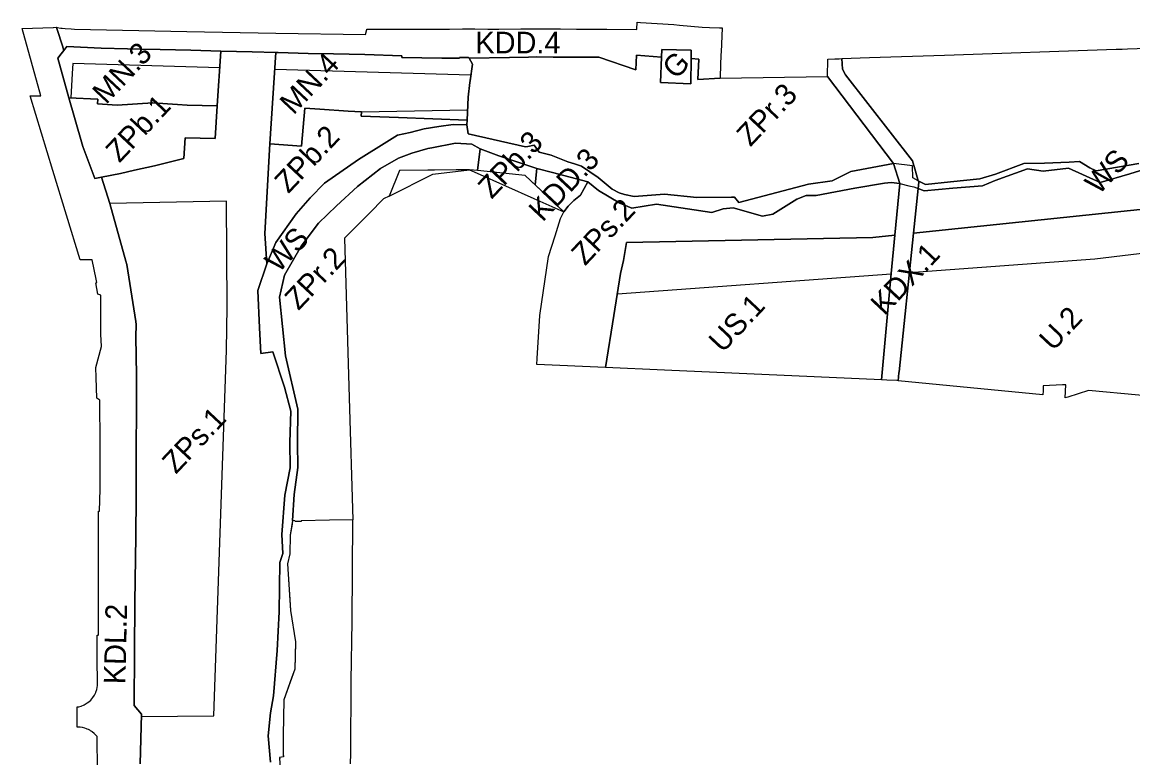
# Model space of a CAD drawing. Extents: x 7425782 to 7428854, y 5550411 to 5553074.
# Drawn here: x 7425924.4 to 7426386.8, y 5550791.4 to 5551098 of the extents above; entities that cross this region are included whole.
import ezdxf

# ---------------------------------------------------------------- set-up
doc = ezdxf.new("R2010")
doc.units = 0
for name, color, linetype in [('LIN_Linie rozgraniczajace WS', 7, 'Continuous'), ('LIN_linie_rozgraniczajace', 7, 'Continuous'), ('LIN_nieprzekraczalna linia zabudowy', 7, 'Continuous'), ('tereny MPZP_PRADNIK_CZERWONY_NACZELNA', 7, 'Continuous'), ('TXT_oznaczenia przeznaczen', 7, 'Continuous')]:
    doc.layers.add(name, color=color, linetype=linetype)

msp = doc.modelspace()

# ---------------------------------------------------------------- linework, layer by layer
at = {"layer": 'LIN_Linie rozgraniczajace WS'}
for points in [[(7426297.5, 5551031.91), (7426295.16, 5551033.1), (7426295.12, 5551038.07), (7426287.1, 5551039.04)], [(7426289.82, 5551030.77), (7426293.58, 5551029.75), (7426295.69, 5551029.3), (7426297.42, 5551028.65)]]:
    msp.add_lwpolyline(points, dxfattribs=at)
at = {"layer": 'LIN_linie_rozgraniczajace'}
for points in [[(7426215.8, 5551095.6), (7426215.39, 5551085.51), (7426215.34, 5551084.42), (7426214.98, 5551075.35), (7426214.95, 5551074.7), (7426214.95, 5551074.69), (7426214.94, 5551074.57), (7426214.94, 5551074.57), (7426205.64, 5551074.12), (7426206.09, 5551082.55), (7426202.86, 5551082.78), (7426202.86, 5551086.29), (7426190.75, 5551086.61), (7426190.63, 5551083.44), (7426180.21, 5551084.26), (7426179.84, 5551078.14), (7426164.44, 5551083.38), (7426145.43, 5551083.43), (7426138.5, 5551083.48), (7426135.17, 5551083.31), (7426127.25, 5551083.21), (7426110.43, 5551082.92), (7426110.23, 5551083.26), (7426106.54, 5551083.3), (7426106.49, 5551082.9), (7426099.18, 5551083.01), (7426082.44, 5551083.24), (7426082.45, 5551083.98), (7426067.06, 5551084.42), (7426053.98, 5551084.79), (7426043.49, 5551084.97), (7426031.04, 5551085.35), (7426030.05, 5551085.39), (7426020.19, 5551085.58), (7426007.07, 5551085.94), (7425994.58, 5551086.3), (7425981.88, 5551086.56), (7425973.98, 5551086.7), (7425968.18, 5551086.79), (7425957.28, 5551087.07), (7425943.02, 5551087.82), (7425941.71, 5551086.16), (7425941.19, 5551088.09), (7425938.94, 5551094.9), (7425938.67, 5551095.85), (7425938.67, 5551095.85), (7425938.69, 5551095.85), (7425938.72, 5551095.84), (7425938.98, 5551095.8), (7425940.5, 5551095.53), (7425940.5, 5551095.53), (7425941.08, 5551095.46), (7425942.36, 5551095.32), (7425944.84, 5551095.14), (7425946.25, 5551095.1), (7425946.25, 5551095.1), (7425992.94, 5551094.01), (7426029.97, 5551093.42), (7426067.31, 5551092.83), (7426067.73, 5551094.38), (7426067.8, 5551094.65), (7426067.84, 5551094.78), (7426067.85, 5551094.81), (7426067.89, 5551094.98), (7426097.22, 5551095.1), (7426098.27, 5551095.1), (7426102.29, 5551095.11), (7426107.73, 5551095.13), (7426109.94, 5551095.14), (7426111.53, 5551095.14), (7426111.54, 5551095.14), (7426111.55, 5551095.14), (7426112.79, 5551095.14), (7426112.85, 5551095.14), (7426118.27, 5551095.11), (7426122.78, 5551095.09), (7426132.03, 5551095.12), (7426148.58, 5551095.17), (7426155.17, 5551095.11), (7426155.17, 5551095.11), (7426160.39, 5551095.07), (7426167.87, 5551095.01), (7426180.28, 5551094.91), (7426180.28, 5551094.91), (7426180.29, 5551094.99), (7426180.29, 5551095), (7426180.29, 5551095.01), (7426180.5, 5551097.95), (7426181.8, 5551097.87), (7426195.75, 5551097), (7426198.06, 5551096.78), (7426207.49, 5551095.89), (7426207.53, 5551095.88), (7426210.49, 5551095.78), (7426214.7, 5551095.64)], [(7426007.07, 5551085.94), (7426005.64, 5551063.03), (7425993.14, 5551063.4), (7425989.01, 5551063.61), (7425978.85, 5551064.28), (7425963.96, 5551063.32), (7425955.74, 5551063.87), (7425955.87, 5551065.84), (7425943.81, 5551066.48), (7425939.19, 5551082.96), (7425940.63, 5551084.79), (7425941.71, 5551086.16), (7425943.02, 5551087.82), (7425957.28, 5551087.07), (7425968.18, 5551086.79), (7425973.98, 5551086.7), (7425981.88, 5551086.56), (7425994.58, 5551086.3)], [(7426110.43, 5551082.92), (7426111.9, 5551080.41), (7426110.91, 5551073.53), (7426110.81, 5551072.81), (7426110.08, 5551066.7), (7426109.62, 5551057.17), (7426081.04, 5551058.3), (7426065.52, 5551058.75), (7426065.63, 5551060.55), (7426060.18, 5551060.89), (7426048.37, 5551061.72), (7426042.01, 5551062.19), (7426040.71, 5551046.28), (7426027.51, 5551047.29), (7426030.05, 5551085.39), (7426031.04, 5551085.35), (7426043.49, 5551084.97), (7426053.98, 5551084.79), (7426067.06, 5551084.42), (7426082.45, 5551083.98), (7426082.44, 5551083.24), (7426099.18, 5551083.01), (7426106.49, 5551082.9), (7426106.54, 5551083.3), (7426110.23, 5551083.26)], [(7426190.63, 5551083.44), (7426190.15, 5551072.79), (7426202.79, 5551072.25), (7426202.86, 5551082.78), (7426206.09, 5551082.55), (7426205.64, 5551074.12), (7426214.94, 5551074.57), (7426214.94, 5551074.57), (7426259.75, 5551075.32), (7426287.1, 5551039.04), (7426269.36, 5551035.67), (7426261.64, 5551031.9), (7426251.76, 5551030.52), (7426222.72, 5551022.82), (7426220.95, 5551025.02), (7426219.72, 5551025.01), (7426205.23, 5551024.86), (7426191.78, 5551026.27), (7426179.13, 5551025.37), (7426175.11, 5551026.19), (7426172.96, 5551026.84), (7426170.03, 5551028.39), (7426164.25, 5551033.26), (7426157.29, 5551038.02), (7426154.32, 5551038.89), (7426151.51, 5551039.82), (7426148.75, 5551040.91), (7426144.59, 5551042.59), (7426139.7, 5551043.77), (7426137.53, 5551046.7), (7426134.97, 5551046.1), (7426133.89, 5551046.07), (7426110.03, 5551051.47), (7426109.52, 5551055.15), (7426109.62, 5551057.17), (7426110.08, 5551066.7), (7426110.81, 5551072.81), (7426110.91, 5551073.53), (7426111.9, 5551080.41), (7426110.43, 5551082.92), (7426127.25, 5551083.21), (7426135.17, 5551083.31), (7426138.5, 5551083.48), (7426145.43, 5551083.43), (7426164.44, 5551083.38), (7426179.84, 5551078.14), (7426180.21, 5551084.26)], [(7426202.86, 5551082.78), (7426202.79, 5551072.25), (7426190.15, 5551072.79), (7426190.63, 5551083.44), (7426190.75, 5551086.61), (7426202.86, 5551086.29)], [(7426289.39, 5550951.87), (7426289.12, 5550948.57), (7426288.53, 5550948.63), (7426284.35, 5550948.81), (7426282.17, 5550948.91), (7426286.21, 5550993.18), (7426287.75, 5551009.24), (7426289.82, 5551030.77), (7426287.1, 5551039.04), (7426259.75, 5551075.32), (7426259.85, 5551082.6), (7426262.77, 5551082.69), (7426264.5, 5551082.75), (7426265.69, 5551082.79), (7426265.69, 5551082.79), (7426265.99, 5551078.4), (7426267.13, 5551076), (7426295.12, 5551040.16), (7426296.35, 5551035.89), (7426297.5, 5551031.91), (7426297.69, 5551031.25), (7426297.42, 5551028.65), (7426295.49, 5551010.06), (7426289.51, 5550952.33)], [(7426005.64, 5551063.03), (7426004.79, 5551049.53), (7425992.29, 5551049.82), (7425991.74, 5551041.19), (7425979.5, 5551038.1), (7425971.23, 5551036.23), (7425965.37, 5551034.91), (7425957.43, 5551033.37), (7425954.62, 5551032.82), (7425949.65, 5551046.1), (7425946.12, 5551058.23), (7425943.81, 5551066.48), (7425955.87, 5551065.84), (7425955.74, 5551063.87), (7425963.96, 5551063.32), (7425978.85, 5551064.28), (7425989.01, 5551063.61), (7425993.14, 5551063.4)], [(7426109.62, 5551057.17), (7426109.52, 5551055.15), (7426103.78, 5551055.26), (7426097.83, 5551054.54), (7426091.71, 5551053.53), (7426086, 5551052.04), (7426080.63, 5551050.93), (7426076.28, 5551048.15), (7426064.43, 5551040.8), (7426050.28, 5551030.82), (7426044.36, 5551024.77), (7426038.41, 5551018.08), (7426030.06, 5551006.1), (7426026.26, 5550997.32), (7426025.43, 5551009.92), (7426027.51, 5551047.29), (7426040.71, 5551046.28), (7426042.01, 5551062.19), (7426048.37, 5551061.72), (7426060.18, 5551060.89), (7426065.63, 5551060.55), (7426065.52, 5551058.75), (7426081.04, 5551058.3)], [(7426115.04, 5551045.2), (7426114.02, 5551036.11), (7426110.63, 5551036.45), (7426105.05, 5551036.41), (7426081.5, 5551036.22), (7426077.23, 5551025.48), (7426074.88, 5551024.29), (7426069.02, 5551018.4), (7426058.65, 5551007.98), (7426060.56, 5550941.47), (7426062.03, 5550890.54), (7426052.4, 5550890.39), (7426040.5, 5550890.2), (7426040.52, 5550889.93), (7426038.02, 5550889.95), (7426037.95, 5550890.16), (7426037, 5550890.25), (7426037, 5550890.25), (7426037.7, 5550901.21), (7426039.13, 5550912.4), (7426039, 5550922.67), (7426039.23, 5550936.74), (7426034.08, 5550958.93), (7426031.6, 5550983.36), (7426033.64, 5550992.58), (7426040.62, 5551004.69), (7426047.82, 5551014.27), (7426055.24, 5551021.39), (7426064.05, 5551029.53), (7426073.55, 5551037.01), (7426081.06, 5551041.3), (7426086.68, 5551043.41), (7426093.32, 5551045.35), (7426095.01, 5551045.64), (7426104.86, 5551047.6), (7426111.59, 5551047.15)], [(7426138.67, 5551037.01), (7426137.97, 5551030.23), (7426133.83, 5551034.14), (7426114.02, 5551036.11), (7426115.04, 5551045.2), (7426122.91, 5551042.26)], [(7426159.96, 5551031.38), (7426156.85, 5551025.84), (7426154.07, 5551023.59), (7426151.74, 5551021.3), (7426149.94, 5551018.93), (7426137.97, 5551030.23), (7426138.67, 5551037.01), (7426145.22, 5551035.28)], [(7426173.17, 5551022.6), (7426178.19, 5551020.44), (7426188.54, 5551022.09), (7426211.52, 5551018.65), (7426216.26, 5551020.12), (7426220.36, 5551020.54), (7426232.69, 5551017.15), (7426236.9, 5551017.95), (7426246.88, 5551024.24), (7426250.8, 5551025.73), (7426254.93, 5551025.78), (7426271.11, 5551028.73), (7426283.4, 5551030.81), (7426286.14, 5551031.16), (7426289.82, 5551030.77), (7426287.75, 5551009.24), (7426278.49, 5551008.25), (7426175.98, 5551006.17), (7426174.73, 5550998.7), (7426173.57, 5550993.17), (7426170.73, 5550975.7), (7426167.26, 5550954.09), (7426138.63, 5550955.38), (7426138.79, 5550957.78), (7426139.97, 5550975.69), (7426143.56, 5551000.38), (7426146.26, 5551008.87), (7426148.58, 5551016.14), (7426148.58, 5551016.14), (7426149.94, 5551018.93), (7426151.74, 5551021.3), (7426154.07, 5551023.59), (7426156.85, 5551025.84), (7426159.96, 5551031.38), (7426164.34, 5551027.84)], [(7426425.64, 5550954.9), (7426424, 5550939.27), (7426410.3, 5550940.56), (7426368.28, 5550944.5), (7426359.7, 5550941.77), (7426358.59, 5550941.42), (7426358.97, 5550946.87), (7426357.5, 5550946.8), (7426349.51, 5550946.41), (7426349.44, 5550944.41), (7426349.38, 5550942.63), (7426289.12, 5550948.57), (7426289.39, 5550951.87), (7426289.51, 5550952.33), (7426295.49, 5551010.06), (7426429.66, 5551024.14), (7426426.02, 5550961.54), (7426426.02, 5550961.54), (7426425.81, 5550957.91)], [(7426282.17, 5550948.91), (7426191.82, 5550952.98), (7426167.26, 5550954.09), (7426170.73, 5550975.7), (7426173.57, 5550993.17), (7426174.73, 5550998.7), (7426175.98, 5551006.17), (7426278.49, 5551008.25), (7426287.75, 5551009.24), (7426286.21, 5550993.18)]]:
    msp.add_lwpolyline(points, close=True, dxfattribs=at)
for points in [[(7425955.84, 5550771.93), (7425955.61, 5550800.27), (7425955.07, 5550800.85), (7425954.32, 5550801.6), (7425953.58, 5550802.22), (7425953.43, 5550802.34), (7425953.43, 5550802.34), (7425952.86, 5550802.71), (7425952.55, 5550802.91), (7425952.55, 5550802.91), (7425951.97, 5550803.19), (7425951.52, 5550803.41), (7425951.52, 5550803.41), (7425951.21, 5550803.53), (7425950.52, 5550803.78), (7425949.54, 5550804.02), (7425948.52, 5550804.19), (7425947.31, 5550804.22), (7425947.32, 5550810.46), (7425947.32, 5550811.37), (7425947.32, 5550812.63), (7425947.57, 5550812.66), (7425947.95, 5550812.71), (7425948.97, 5550813.01), (7425950.16, 5550813.52), (7425951.07, 5550814.03), (7425951.28, 5550814.15), (7425951.48, 5550814.3), (7425952.09, 5550814.75), (7425952.98, 5550815.51), (7425953.8, 5550816.52), (7425954.45, 5550817.47), (7425955.01, 5550818.64), (7425955.01, 5550818.64), (7425955.06, 5550818.77), (7425955.5, 5550819.95), (7425955.8, 5550821.51), (7425955.68, 5550833.66), (7425955.59, 5550842.56), (7425956.07, 5550842.6), (7425956.22, 5550842.61), (7425956.22, 5550843.47), (7425956.19, 5550858.72), (7425956.19, 5550875.69), (7425956.19, 5550875.69), (7425956.15, 5550894.19), (7425956.66, 5550894.27), (7425956.91, 5550903.41), (7425956.85, 5550914.45), (7425956.83, 5550917.11), (7425956.83, 5550917.11), (7425956.82, 5550922.12), (7425956.78, 5550940.39), (7425955.52, 5550941.23), (7425955.23, 5550949.91), (7425955.09, 5550954.12), (7425957.42, 5550962.88), (7425957.2, 5550967.97), (7425957.2, 5550967.97), (7425957.16, 5550984.24), (7425955.93, 5550984.67), (7425955.09, 5550989.29), (7425955.24, 5550989.33), (7425955.51, 5550989.42), (7425955.22, 5550990.82), (7425953.57, 5550998.88), (7425949.01, 5550998.91), (7425948.54, 5550998.91), (7425937.17, 5551036.17), (7425927.7, 5551067.22), (7425932.1, 5551067.33), (7425932.1, 5551067.33), (7425924.41, 5551095.28), (7425937.34, 5551095.8), (7425937.43, 5551095.8), (7425938.67, 5551095.85), (7425938.67, 5551095.85), (7425938.94, 5551094.9), (7425941.19, 5551088.09), (7425941.71, 5551086.16), (7425940.63, 5551084.79), (7425939.19, 5551082.96), (7425943.81, 5551066.48), (7425946.12, 5551058.23), (7425949.65, 5551046.1), (7425954.62, 5551032.82), (7425957.43, 5551033.37), (7425960.93, 5551022.38), (7425967.55, 5550998.37), (7425967.91, 5550997.05), (7425971.71, 5550973.18), (7425971.85, 5550971.99), (7425971.77, 5550966.88), (7425972.01, 5550950.87), (7425971.95, 5550946.48), (7425971.98, 5550940.06), (7425971.93, 5550935.95), (7425971.89, 5550920.72), (7425971.8, 5550900), (7425971.7, 5550883.82), (7425971.36, 5550856.12), (7425971.17, 5550835.7), (7425970.98, 5550813.2), (7425972.55, 5550811.37), (7425974.01, 5550809.64), (7425973.52, 5550788.95)], [(7426389.24, 5551039.02), (7426371.6, 5551036.01), (7426368.87, 5551037.32), (7426364.62, 5551039.92), (7426360.23, 5551039.63), (7426349.97, 5551039.18), (7426341.46, 5551039.07), (7426329.59, 5551034.67), (7426323.16, 5551032.62), (7426310.86, 5551031.44), (7426300.5, 5551030.37), (7426297.5, 5551031.91), (7426296.35, 5551035.89), (7426295.12, 5551040.16), (7426267.13, 5551076), (7426265.99, 5551078.4), (7426265.69, 5551082.79), (7426265.69, 5551082.79), (7426277.13, 5551083.18), (7426308.37, 5551084.24), (7426379.8, 5551086.66), (7426382.13, 5551086.74), (7426382.4, 5551086.75), (7426384.54, 5551086.82), (7426470.47, 5551089.73)], [(7425973.52, 5550788.95), (7425974.01, 5550809.64), (7425972.55, 5550811.37), (7425970.98, 5550813.2), (7425971.17, 5550835.7), (7425971.36, 5550856.12), (7425971.7, 5550883.82), (7425971.8, 5550900), (7425971.89, 5550920.72), (7425971.93, 5550935.95), (7425971.98, 5550940.06), (7425971.95, 5550946.48), (7425972.01, 5550950.87), (7425971.77, 5550966.88), (7425971.85, 5550971.99), (7425971.71, 5550973.18), (7425967.91, 5550997.05), (7425967.55, 5550998.37), (7425960.93, 5551022.38), (7425957.43, 5551033.37), (7425965.37, 5551034.91), (7425971.23, 5551036.23), (7425979.5, 5551038.1), (7425991.74, 5551041.19), (7425992.29, 5551049.82), (7426004.79, 5551049.53), (7426005.64, 5551063.03), (7426007.07, 5551085.94), (7426020.19, 5551085.58), (7426030.05, 5551085.39), (7426027.51, 5551047.29), (7426025.43, 5551009.92), (7426026.26, 5550997.32), (7426022.51, 5550986.21), (7426023.24, 5550970.66), (7426023.76, 5550959.97), (7426028.69, 5550960.6), (7426033.55, 5550945.9), (7426036.31, 5550935.93), (7426035.81, 5550922.75), (7426035.96, 5550912.33), (7426033.82, 5550900.85), (7426032.55, 5550884.46), (7426032.9, 5550876.57), (7426031.7, 5550872.81), (7426031.45, 5550852.33), (7426030.52, 5550836.14), (7426029.01, 5550817.2), (7426027.76, 5550810.2), (7426026.76, 5550800.54), (7426027.84, 5550789.67)], [(7426027.84, 5550789.67), (7426026.76, 5550800.54), (7426027.76, 5550810.2), (7426029.01, 5550817.2), (7426030.52, 5550836.14), (7426031.45, 5550852.33), (7426031.7, 5550872.81), (7426032.9, 5550876.57), (7426032.55, 5550884.46), (7426033.82, 5550900.85), (7426035.96, 5550912.33), (7426035.81, 5550922.75), (7426036.31, 5550935.93), (7426033.55, 5550945.9), (7426028.69, 5550960.6), (7426023.76, 5550959.97), (7426023.24, 5550970.66), (7426022.51, 5550986.21), (7426026.26, 5550997.32), (7426030.06, 5551006.1), (7426038.41, 5551018.08), (7426044.36, 5551024.77), (7426050.28, 5551030.82), (7426064.43, 5551040.8), (7426076.28, 5551048.15), (7426080.63, 5551050.93), (7426086, 5551052.04), (7426091.71, 5551053.53), (7426097.83, 5551054.54), (7426103.78, 5551055.26), (7426109.52, 5551055.15), (7426110.03, 5551051.47), (7426133.89, 5551046.07), (7426134.97, 5551046.1), (7426137.53, 5551046.7), (7426139.7, 5551043.77), (7426144.59, 5551042.59), (7426148.75, 5551040.91), (7426151.51, 5551039.82), (7426154.32, 5551038.89), (7426157.29, 5551038.02), (7426164.25, 5551033.26), (7426170.03, 5551028.39), (7426172.96, 5551026.84), (7426175.11, 5551026.19), (7426179.13, 5551025.37), (7426191.78, 5551026.27), (7426205.23, 5551024.86), (7426219.72, 5551025.01), (7426220.95, 5551025.02), (7426222.72, 5551022.82), (7426251.76, 5551030.52), (7426261.64, 5551031.9), (7426269.36, 5551035.67), (7426287.1, 5551039.04), (7426289.82, 5551030.77), (7426286.14, 5551031.16), (7426283.4, 5551030.81), (7426271.11, 5551028.73), (7426254.93, 5551025.78), (7426250.8, 5551025.73), (7426246.88, 5551024.24), (7426236.9, 5551017.95), (7426232.69, 5551017.15), (7426220.36, 5551020.54), (7426216.26, 5551020.12), (7426211.52, 5551018.65), (7426188.54, 5551022.09), (7426178.19, 5551020.44), (7426173.17, 5551022.6), (7426164.34, 5551027.84), (7426159.96, 5551031.38), (7426145.22, 5551035.28), (7426138.67, 5551037.01), (7426122.91, 5551042.26), (7426115.04, 5551045.2), (7426111.59, 5551047.15), (7426104.86, 5551047.6), (7426095.01, 5551045.64), (7426093.32, 5551045.35), (7426086.68, 5551043.41), (7426081.06, 5551041.3), (7426073.55, 5551037.01), (7426064.05, 5551029.53), (7426055.24, 5551021.39), (7426047.82, 5551014.27), (7426040.62, 5551004.69), (7426033.64, 5550992.58), (7426031.6, 5550983.36), (7426034.08, 5550958.93), (7426039.23, 5550936.74), (7426039, 5550922.67), (7426039.13, 5550912.4), (7426037.7, 5550901.21), (7426037, 5550890.25), (7426037, 5550890.25), (7426036.75, 5550888.82), (7426035.96, 5550884.17), (7426035.79, 5550876.45), (7426035.79, 5550876.45), (7426034.84, 5550872.23), (7426036.01, 5550855.24), (7426036.18, 5550852.78), (7426038.15, 5550839.74), (7426038.14, 5550839.33), (7426037.87, 5550828.43), (7426036.66, 5550825.01), (7426033.34, 5550815.62), (7426033.04, 5550800.85), (7426033.05, 5550793.24), (7426033.09, 5550792.55), (7426033.13, 5550791.84), (7426032.4, 5550791.7), (7426031.6, 5550791.55), (7426031.62, 5550791.15)], [(7426393.57, 5551037.22), (7426385.51, 5551034.78), (7426373.25, 5551031.11), (7426359.98, 5551037.18), (7426349.46, 5551035.87), (7426342.92, 5551036.85), (7426329.55, 5551031.93), (7426324.28, 5551029.77), (7426311.84, 5551028.73), (7426299.95, 5551027.71), (7426297.42, 5551028.65), (7426297.69, 5551031.25), (7426297.5, 5551031.91), (7426300.5, 5551030.37), (7426310.86, 5551031.44), (7426323.16, 5551032.62), (7426329.59, 5551034.67), (7426341.46, 5551039.07), (7426349.97, 5551039.18), (7426360.23, 5551039.63), (7426364.62, 5551039.92), (7426368.87, 5551037.32), (7426371.6, 5551036.01), (7426389.24, 5551039.02)], [(7426429.66, 5551024.14), (7426295.49, 5551010.06), (7426297.42, 5551028.65), (7426299.95, 5551027.71), (7426311.84, 5551028.73), (7426324.28, 5551029.77), (7426329.55, 5551031.93), (7426342.92, 5551036.85), (7426349.46, 5551035.87), (7426359.98, 5551037.18), (7426373.25, 5551031.11), (7426385.51, 5551034.78), (7426393.57, 5551037.22)]]:
    msp.add_lwpolyline(points, dxfattribs=at)
at = {"layer": 'LIN_nieprzekraczalna linia zabudowy'}
for p, q in [((7426022.55, 5551083.2), (7426022.55, 5551083.2)), ((7426111.25, 5551075.86), (7426029.58, 5551078.3)), ((7426065.63, 5551060.55), (7426109.83, 5551061.46))]:
    msp.add_line(p, q, dxfattribs=at)
for points in [[(7426006.67, 5551078.95), (7425945.47, 5551080.75), (7425945.2, 5551076.55), (7425944.65, 5551066.43)], [(7426110.95, 5551074), (7426110.96, 5551074.08)], [(7426542.71, 5551051.69), (7426533.71, 5551051.41), (7426518.28, 5551048.79), (7426520.05, 5551033.63), (7426521.96, 5551017.38), (7426371.04, 5550999.14), (7426293.78, 5550993.52)], [(7425973.98, 5550808.58), (7426004.18, 5550808.87), (7426009.51, 5550961.34), (7426009.71, 5550979.28), (7426009.48, 5551023.32), (7425960.93, 5551022.38)], [(7426286.19, 5550992.97), (7426172.19, 5550984.68)]]:
    msp.add_lwpolyline(points, dxfattribs=at)
at = {"layer": 'tereny MPZP_PRADNIK_CZERWONY_NACZELNA'}
for p, q in [((7426077.23, 5551025.48), (7426095.4, 5551034.68)), ((7426095.4, 5551034.68), (7426110.63, 5551036.45)), ((7426110.63, 5551036.45), (7426113.89, 5551034.99)), ((7426113.89, 5551034.99), (7426137.38, 5551024.53)), ((7426149.94, 5551018.93), (7426133.83, 5551034.14)), ((7426137.38, 5551024.53), (7426149.94, 5551018.93)), ((7426062.03, 5550890.54), (7426052.4, 5550890.39)), ((7426061.82, 5550848.26), (7426062.03, 5550890.54)), ((7426061.16, 5550788.96), (7426061.21, 5550793.2))]:
    msp.add_line(p, q, dxfattribs=at)
for points in [[(7426110.63, 5551036.45), (7426081.5, 5551036.22), (7426077.23, 5551025.48)], [(7426133.83, 5551034.14), (7426114.02, 5551036.11), (7426110.63, 5551036.45)], [(7426052.4, 5550890.39), (7426040.5, 5550890.2), (7426040.52, 5550889.93), (7426038.02, 5550889.95), (7426037.95, 5550890.16), (7426037, 5550890.25), (7426035.96, 5550884.17), (7426035.79, 5550876.45), (7426034.84, 5550872.23), (7426036.18, 5550852.78), (7426038.15, 5550839.74), (7426037.87, 5550828.43), (7426033.34, 5550815.62), (7426033.04, 5550800.85), (7426033.05, 5550793.24), (7426033.13, 5550791.84), (7426031.6, 5550791.55), (7426032.6, 5550771.29)], [(7426061.21, 5550793.2), (7426061.42, 5550823.45), (7426061.82, 5550848.26)]]:
    msp.add_lwpolyline(points, dxfattribs=at)

# ---------------------------------------------------------------- texts
at = {"layer": 'TXT_oznaczenia przeznaczen'}
for s, rotation, p in [('KDD.4', 359.948, (7426113.08, 5551084.99)), ('MN.3', 46.7736, (7425959.36, 5551063.34)), ('MN.4', 46.7736, (7426037.37, 5551059.02)), ('G', 46.7736, (7426196.66, 5551073.72)), ('ZPr.3', 46.7736, (7426227.58, 5551045.77)), ('ZPb.1', 46.7736, (7425964.9, 5551039.06)), ('ZPb.2', 46.7736, (7426035.23, 5551026.24)), ('ZPb.3', 46.7967, (7426119.87, 5551023.96)), ('KDD.3', 46.7736, (7426141.06, 5551014.39)), ('WS', 46.7736, (7426372.61, 5551025.69)), ('ZPs.2', 46.7736, (7426158.76, 5550996.16)), ('WS', 46.7736, (7426031.17, 5550993.15)), ('ZPr.2', 46.7736, (7426039.44, 5550977.54)), ('KDX.1', 46.7736, (7426283.36, 5550975.35)), ('US.1', 46.7736, (7426215.98, 5550959.81)), ('U.2', 46.7736, (7426353.57, 5550960.51)), ('ZPs.1', 46.7736, (7425988.41, 5550909.35)), ('KDL.2', 88.6935, (7425967.36, 5550822.03))]:
    msp.add_text(s, height=9, rotation=rotation, dxfattribs=at).set_placement(p)

doc.saveas('drawing.dxf')
